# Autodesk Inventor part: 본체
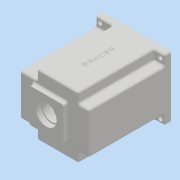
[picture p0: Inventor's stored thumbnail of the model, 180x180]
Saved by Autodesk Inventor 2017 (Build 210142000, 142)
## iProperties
Part Number: 본체
Material: 일반
Document SubType Name: Modeling
Designer: MRC
Density: 1 g/cm^3
Appearance: 기본값
Author: MRC
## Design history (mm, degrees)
sketch "스케치2"
  geometry: L1 (60, 49)-(-50, 49); L2 (-50, 49)-(-50, -49); L3 (-50, -49)-(60, -49); L4 (60, -49)-(60, 49); 2 further points
  constraints: 8 end point, 2 parallel, 1 horizontal, 1 horizontal alignment, 1 midpoint, 1 perpendicular
  dimensions: "d2" = 110 distance of L1.start L1.end; "d3" = 98 distance of L1.end L2.end; "d4" = 50 distance of point (-50, 0) point (0, 0)
extrude "돌출1" new body sketch "스케치2" stored distance "d5" = 130; taper "d6" = 0 deg
sketch "스케치3" dims "d7" = 90
  geometry: L1 (-53, -26)-(-36.729, -26); L2 (-36.729, -26)-(-36.729, 26); L3 (-36.729, 26)-(-53, 26); L4 (-53, 26)-(-53, -26); 3 further points
  constraints: 8 end point, 2 parallel, 1 coincident, 1 horizontal, 1 horizontal alignment, 1 midpoint, 1 perpendicular, 3 other
  dimensions: "d8" = 52 distance of L3.end L1.start; "d9" = 53 distance of point (0, 0) point (-53, 0)
extrude "돌출2" cut sketch "스케치3" distance "d10" = 9; taper "d11" = 0 deg
sketch "스케치4"
  geometry: L1 (-53, 26)-(-36.729, 26) reference; L2 (-53, -26)-(-53, 26) reference; L3 (-36.729, -26)-(-53, -26) reference; L4 (-35.143, -23)-(-50, -23); L5 (-50, -23)-(-50, 23); L6 (-50, 23)-(-35.143, 23); A1 r 45 centre (0, 0) between (-36.729, -26) and (-36.729, 26) reference; A2 r 42 centre (0, 0) between (-35.143, -23) and (-35.143, 23)
  constraints: 6 end point, 2 point on circle, 1 centre point, 3 other
  dimensions: "d12" = 3 radial gap between concentric circles of A1 A2
extrude "돌출3" cut sketch "스케치4" distance "d13" = 112; taper "d14" = 0 deg
sketch "스케치6"
  geometry: C1 r 21 at (-11, 0); C2 r 15 at (20, 0); A1 r 42 centre (0, 0) between (-35.143, -23) and (-35.143, 23) reference
  constraints: 2 centre point, 2 horizontal alignment
  dimensions: "d15" = 42 diameter of C1; "d16" = 11 distance of A1.centre C1.centre; "d17" = 30 diameter of C2; "d18" = 20 distance of A1.centre C2.centre
extrude "돌출4" join sketch "스케치6" distance "d19" = 7; taper "d20" = 0 deg
sketch "스케치8"
  geometry: C1 r 17.5 at (-11, 0); A1 r 21 centre (-11, 0) between (7.984, 8.978) and (7.984, -8.978) reference; 1 further point
  constraints: 1 centre point, 1 coincident
  dimensions: "d23" = 35 diameter of C1
extrude "돌출5" cut sketch "스케치8" distance "d24" = 10; taper "d25" = 0 deg
sketch "스케치9"
  geometry: C1 r 11 at (20, 0); A1 r 15 centre (20, 0) between (7.984, -8.978) and (7.984, 8.978) reference; 1 further point
  constraints: 1 centre point, 1 coincident
  dimensions: "d26" = 22 diameter of C1
extrude "돌출6" cut sketch "스케치9" distance "d27" = 7; taper "d28" = 0 deg
sketch "스케치10"
  geometry: C1 r 11 at (0, 0) reference; C2 r 9.5 at (0, 0); 1 further point
  constraints: 1 centre point, 1 coincident
  dimensions: "d29" = 19 diameter of C2
extrude "돌출7" cut sketch "스케치10" distance "d30" = 3; taper "d31" = 0 deg
sketch "스케치11"
  geometry: C1 r 17.5 at (0, 0) reference; C2 r 14 at (0, 0); 1 further point
  constraints: 1 centre point, 1 coincident
  dimensions: "d32" = 28 diameter of C2
extrude "돌출8" cut sketch "스케치11" stored distance "d33" = 3; taper "d34" = 0 deg
sketch "스케치12"
  geometry: L1 (-38, -27)-(16, -27); L2 (16, -27)-(16, 27); L3 (16, 27)-(-38, 27); L4 (-38, 27)-(-38, -27); L5 (-38, -27)-(16, 27); L6 (16, -27)-(-38, 27); C1 r 14 at (-11, 0) reference; 1 further point
  constraints: 12 end point, 2 midpoint, 2 parallel, 1 horizontal, 1 perpendicular
  dimensions: "d35" = 54 distance of L3.end L2.end; "d36" = 54 distance of L2.end L1.end
extrude "돌출9" join sketch "스케치12" distance "d37" = 7; taper "d38" = 0 deg
sketch "스케치13"
  geometry: C1 r 14 at (-11, 0) reference; C2 r 16 at (-11, 0); 1 further point
  constraints: 1 centre point, 1 coincident
  dimensions: "d39" = 32 diameter of C2
extrude "돌출10" cut sketch "스케치13" distance "d40" = 8.3; taper "d41" = 0 deg
chamfer "모따기1" distance "d42" = 0.8; stored, may be unused: second distance "d43" = 2, angle "d44" = 30 deg
fillet "모깎기1" dims "d45" = 0.3
chamfer "모따기2" distance "d46" = 1; stored, may be unused: second distance "d47" = 2, angle "d48" = 30 deg
fillet "모깎기2" dims "d49" = 3
sketch "스케치14"
  geometry: L1 (-4, 36)-(-4, 41.809); L2 (4, 36)-(4, 41.809); A1 r 42 centre (0, 0) between (-35.143, -23) and (-35.143, 23) reference; A2 r 45 centre (0, 0) between (-36.729, -26) and (-36.729, 26) reference; A3 r 4 centre (0, 36) between (-4, 36) and (4, 36); A4 r 42 centre (0, 0) between (4, 41.809) and (-4, 41.809)
  constraints: 6 point on circle, 4 end point, 2 centre point, 2 tangent, 2 vertical, 1 coincident, 1 vertical alignment
  dimensions: "d50" = 8 diameter of A3; "d51" = 36 distance of A3.centre A1.centre
extrude "돌출11" join sketch "스케치14" stored distance "d52" = 8.3; taper "d53" = 0 deg
hole "구멍1" diameter "d56" = 3.242; stored, may be unused: countersink angle "d60" = 90 deg, drill point angle "d62" = 118 deg; dims "d54" = 10, "d55" = 10, "d57" = 7, "d58" = 4, "d59" = 2, "d61" = 9
sketch "스케치15"
  geometry: L1 (-60, -49)-(-33, -49); L2 (-33, -49)-(-33, -33); L3 (-33, -33)-(-60, -33); L4 (-60, -33)-(-60, -49); L5 (50, -49)-(33, -49); L6 (33, -49)-(33, -33); L7 (33, -33)-(50, -33); L8 (50, -33)-(50, -49); 1 further point
  constraints: 16 end point, 4 parallel, 2 horizontal, 2 perpendicular
  dimensions: "d63" = 27 distance of L3.end L2.end; "d64" = 16 distance of L2.end L1.end; "d65" = 17 distance of L6.end L7.end; "d66" = 16 distance of L5.end L6.end
extrude "돌출12" cut sketch "스케치15" distance "d67" = 120; taper "d68" = 0 deg
sketch "스케치16"
  geometry: L1 (0, 0)-(98, 0) reference; C1 r 15 at (49, -89); C2 r 22.5 at (49, -40); 1 further point
  constraints: 2 centre point, 2 vertical alignment
  dimensions: "d69" = 30 diameter of C1; "d70" = 45 diameter of C2; "d71" = 40 distance from line of C2.centre L1; "d72" = 49 distance of C1.centre C2.centre
extrude "돌출13" join sketch "스케치16" distance "d73" = 5; taper "d74" = 0 deg
extrude "돌출14" join sketch "스케치16" distance "d75" = 10; taper "d76" = 0 deg
hole "구멍2" diameter "d79" = 33.376; stored, may be unused: countersink angle "d83" = 90 deg, drill point angle "d85" = 118 deg; dims "d77" = 10, "d78" = 10, "d80" = 70, "d81" = 4, "d82" = 2, "d84" = 77.3
hole "구멍3" diameter "d88" = 20; stored, may be unused: countersink angle "d92" = 90 deg, drill point angle "d94" = 118 deg; dims "d86" = 10, "d87" = 10, "d89" = 70, "d90" = 30, "d91" = 5, "d93" = 77.3
sketch "스케치17"
  geometry: L1 (50, 49)-(-60, 49) reference; L2 (-60, 49)-(-60, -49) reference; C1 r 3.5 at (-53, 42); C2 r 3.5 at (43, 42)
  constraints: 2 centre point, 1 horizontal alignment
  dimensions: "d95" = 7 diameter of C1; "d96" = 7 diameter of C2; "d97" = 96 distance of C2.centre C1.centre; "d98" = 7 distance from line of L2 C1.centre; "d99" = 7 distance from line of L1 C1.centre
extrude "돌출15" cut sketch "스케치17" distance "d100" = 10; taper "d101" = 0 deg
fillet "모깎기3" dims "d102" = 6
fillet "모깎기4" dims "d103" = 3
fillet "모깎기5" dims "d104" = 3
fillet "모깎기6" dims "d105" = 3
fillet "모깎기7" dims "d106" = 3
fillet "모깎기8" dims "d107" = 3
fillet "모깎기9" dims "d108" = 3
fillet "모깎기10" dims "d109" = 3
fillet "모깎기11" dims "d110" = 3
fillet "모깎기12" dims "d111" = 3
fillet "모깎기13" dims "d112" = 3
fillet "모깎기14" dims "d113" = 3
fillet "모깎기15" dims "d114" = 3
fillet "모깎기16" dims "d115" = 6
chamfer "모따기3" distance "d116" = 1; stored, may be unused: second distance "d117" = 2, angle "d118" = 30 deg
fillet "모깎기17" dims "d119" = 3
fillet "모깎기18" dims "d120" = 3
fillet "모깎기19" dims "d121" = 3
fillet "모깎기20" dims "d122" = 3
fillet "모깎기21" dims "d123" = 0.3
sketch "스케치19"
  geometry: L1 (0, -130)-(21, -130) reference; 2 further points
  constraints: 1 coincident, 1 other
feature "엠보싱1" sketch "스케치19" dims "d125" = 0.5, "d126" = 0
node "솔리드1"
mirror "미러1"
mirror "미러2"
mirror "미러3"
